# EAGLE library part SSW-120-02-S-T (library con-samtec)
THROUGH-HOLE .025" SQ POST SOCKET Source: Samtec SSW.pdf
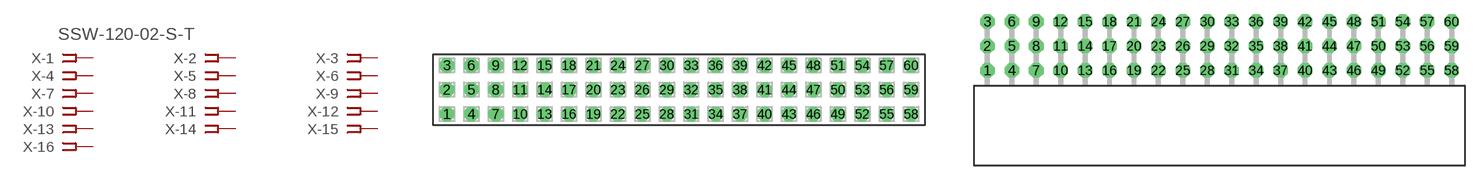
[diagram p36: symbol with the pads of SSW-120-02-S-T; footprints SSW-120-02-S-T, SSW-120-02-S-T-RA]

Designator prefix X; gates -1=FPINV -2=FPIN -3=FPIN -4=FPIN -5=FPIN -6=FPIN -7=FPIN -8=FPIN -9=FPIN -10=FPIN -11=FPIN -12=FPIN -13=FPIN -14=FPIN -15=FPIN -16=FPIN -17=FPIN -18=FPIN -19=FPIN -20=FPIN -21=FPIN -22=FPIN -23=FPIN -24=FPIN -25=FPIN -26=FPIN -27=FPIN -28=FPIN -29=FPIN -30=FPIN -31=FPIN -32=FPIN -33=FPIN -34=FPIN -35=FPIN -36=FPIN -37=FPIN -38=FPIN -39=FPIN -40=FPIN -41=FPIN -42=FPIN -43=FPIN -44=FPIN -45=FPIN -46=FPIN -47=FPIN -48=FPIN -49=FPIN -50=FPIN -51=FPIN -52=FPIN -53=FPIN -54=FPIN -55=FPIN -56=FPIN -57=FPIN -58=FPIN -59=FPIN -60=FPIN

## SSW-120-02-S-T (MPN: SSW-120-02-S-T; OC_FARNELL: unknown; OC_NEWARK: 82P8259)  [SSW-120-02-S-T]
1  -1:1  pas
2  -2:1  pas
3  -3:1  pas
4  -4:1  pas
5  -5:1  pas
6  -6:1  pas
7  -7:1  pas
8  -8:1  pas
9  -9:1  pas
10  -10:1  pas
11  -11:1  pas
12  -12:1  pas
13  -13:1  pas
14  -14:1  pas
15  -15:1  pas
16  -16:1  pas
17  -17:1  pas
18  -18:1  pas
19  -19:1  pas
20  -20:1  pas
21  -21:1  pas
22  -22:1  pas
23  -23:1  pas
24  -24:1  pas
25  -25:1  pas
26  -26:1  pas
27  -27:1  pas
28  -28:1  pas
29  -29:1  pas
30  -30:1  pas
31  -31:1  pas
32  -32:1  pas
33  -33:1  pas
34  -34:1  pas
35  -35:1  pas
36  -36:1  pas
37  -37:1  pas
38  -38:1  pas
39  -39:1  pas
40  -40:1  pas
41  -41:1  pas
42  -42:1  pas
43  -43:1  pas
44  -44:1  pas
45  -45:1  pas
46  -46:1  pas
47  -47:1  pas
48  -48:1  pas
49  -49:1  pas
50  -50:1  pas
51  -51:1  pas
52  -52:1  pas
53  -53:1  pas
54  -54:1  pas
55  -55:1  pas
56  -56:1  pas
57  -57:1  pas
58  -58:1  pas
59  -59:1  pas
60  -60:1  pas

## SSW-120-02-S-TRA (MPN: SSW-120-02-S-T-RA; OC_FARNELL: unknown; OC_NEWARK: 82P8260)  [SSW-120-02-S-T-RA]
Pads as for SSW-120-02-S-T

## Footprint SSW-120-02-S-T (pad centres in mm)
THROUGH-HOLE .025" SQ POST SOCKET Source: Samtec SSW.pdf
drill 1 pad 1.5 octagon: 1 -24.13,-2.54; 2 -24.13,0; 3 -24.13,2.54; 4 -21.59,-2.54; 5 -21.59,0; 6 -21.59,2.54; 7 -19.05,-2.54; 8 -19.05,0; 9 -19.05,2.54; 10 -16.51,-2.54; 11 -16.51,0; 12 -16.51,2.54; 13 -13.97,-2.54; 14 -13.97,0; 15 -13.97,2.54; 16 -11.43,-2.54; 17 -11.43,0; 18 -11.43,2.54; 19 -8.89,-2.54; 20 -8.89,0; 21 -8.89,2.54; 22 -6.35,-2.54; 23 -6.35,0; 24 -6.35,2.54; 25 -3.81,-2.54; 26 -3.81,0; 27 -3.81,2.54; 28 -1.27,-2.54; 29 -1.27,0; 30 -1.27,2.54; 31 1.27,-2.54; 32 1.27,0; 33 1.27,2.54; 34 3.81,-2.54; 35 3.81,0; 36 3.81,2.54; 37 6.35,-2.54; 38 6.35,0; 39 6.35,2.54; 40 8.89,-2.54; 41 8.89,0; 42 8.89,2.54; 43 11.43,-2.54; 44 11.43,0; 45 11.43,2.54; 46 13.97,-2.54; 47 13.97,0; 48 13.97,2.54; 49 16.51,-2.54; 50 16.51,0; 51 16.51,2.54; 52 19.05,-2.54; 53 19.05,0; 54 19.05,2.54; 55 21.59,-2.54; 56 21.59,0; 57 21.59,2.54; 58 24.13,-2.54; 59 24.13,0; 60 24.13,2.54

## Footprint SSW-120-02-S-T-RA (pad centres in mm)
THROUGH-HOLE .025" SQ POST SOCKET Source: Samtec SSW.pdf
drill 1 pad 1.5 octagon: 1 -24.13,1.524; 2 -24.13,4.064; 3 -24.13,6.604; 4 -21.59,1.524; 5 -21.59,4.064; 6 -21.59,6.604; 7 -19.05,1.524; 8 -19.05,4.064; 9 -19.05,6.604; 10 -16.51,1.524; 11 -16.51,4.064; 12 -16.51,6.604; 13 -13.97,1.524; 14 -13.97,4.064; 15 -13.97,6.604; 16 -11.43,1.524; 17 -11.43,4.064; 18 -11.43,6.604; 19 -8.89,1.524; 20 -8.89,4.064; 21 -8.89,6.604; 22 -6.35,1.524; 23 -6.35,4.064; 24 -6.35,6.604; 25 -3.81,1.524; 26 -3.81,4.064; 27 -3.81,6.604; 28 -1.27,1.524; 29 -1.27,4.064; 30 -1.27,6.604; 31 1.27,1.524; 32 1.27,4.064; 33 1.27,6.604; 34 3.81,1.524; 35 3.81,4.064; 36 3.81,6.604; 37 6.35,1.524; 38 6.35,4.064; 39 6.35,6.604; 40 8.89,1.524; 41 8.89,4.064; 42 8.89,6.604; 43 11.43,1.524; 44 11.43,4.064; 45 11.43,6.604; 46 13.97,1.524; 47 13.97,4.064; 48 13.97,6.604; 49 16.51,1.524; 50 16.51,4.064; 51 16.51,6.604; 52 19.05,1.524; 53 19.05,4.064; 54 19.05,6.604; 55 21.59,1.524; 56 21.59,4.064; 57 21.59,6.604; 58 24.13,1.524; 59 24.13,4.064; 60 24.13,6.604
